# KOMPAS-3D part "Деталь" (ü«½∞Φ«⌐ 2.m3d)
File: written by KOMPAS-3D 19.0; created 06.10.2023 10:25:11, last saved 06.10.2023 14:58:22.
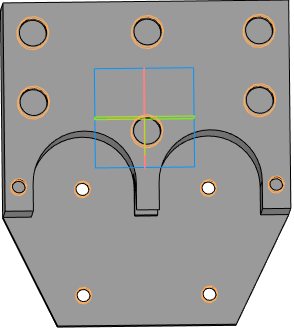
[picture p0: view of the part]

Document properties: Автор: admin; Организация: Hewlett-Packard Company; Полное имя файла: C:\Users\Petrenko-VE\Documents\Большой_2.m3d

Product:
- Part/product: Деталь
    Масса: 13.4529

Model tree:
1. Эскиз:1
2. Элемент выдавливания:1
     Расстояние 1 = 25
3. Эскиз:2  (with: Элемент выдавливания:1)
4. Элемент выдавливания:2
     Расстояние 1 = 100
5. Эскиз:3  (with: Элемент выдавливания:1, Элемент выдавливания:2)
6. Элемент выдавливания:3
     Расстояние 2 = 40
7. Эскиз:4  (with: Элемент выдавливания:3)
8. Элемент выдавливания:4
     Расстояние 1 = 5
9. Эскиз:5  (with: Элемент выдавливания:3)
10. Элемент выдавливания:5
     Расстояние 1 = 5
11. Эскиз:6  (with: Элемент выдавливания:1)
12. Элемент выдавливания:6
     Расстояние 1 = 10
13. Эскиз:7  (with: Элемент выдавливания:5)
14. Элемент выдавливания:7
     Расстояние 2 = 20
15. Эскиз:8  (with: Элемент выдавливания:4)
16. Элемент выдавливания:8
     Расстояние 2 = 20
17. Эскиз:9  (with: Элемент выдавливания:1, Элемент выдавливания:2, Элемент выдавливания:6)
18. Элемент выдавливания:9
     Расстояние 2 = 5
19. Фаска:1  (with: Элемент выдавливания:8, Элемент выдавливания:7)
     Угол = 45; Длина 1 = 1; Длина 2 = 1
20. Эскиз:10  (with: Элемент выдавливания:5, Фаска:1)
21. Элемент выдавливания:10
     Расстояние 2 = 145
22. Эскиз:11  (with: Элемент выдавливания:4, Фаска:1)
23. Элемент выдавливания:11
     Расстояние 2 = 145
24. Эскиз:12  (with: Элемент выдавливания:9, Элемент выдавливания:10, Элемент выдавливания:11)
25. Элемент выдавливания:12
     Расстояние 1 = 105
26. Эскиз:13  (with: Элемент выдавливания:12, Элемент выдавливания:2)
27. Элемент выдавливания:13
     Расстояние 1 = 30
28. Эскиз:14  (with: Элемент выдавливания:9, Элемент выдавливания:12)
29. Элемент выдавливания:14
     Расстояние 1 = 105
30. Эскиз:15  (with: Элемент выдавливания:1, Элемент выдавливания:6)
31. Элемент выдавливания:15
     Расстояние 1 = 12
32. Эскиз:16  (with: Элемент выдавливания:15)
33. Элемент выдавливания:16
     Расстояние 2 = 40.25
34. Эскиз:17  (with: Элемент выдавливания:9, Элемент выдавливания:12)
35. Элемент выдавливания:17
     Расстояние 1 = 105
36. Эскиз:18  (with: Элемент выдавливания:1, Элемент выдавливания:6)
37. Элемент выдавливания:18
     Расстояние 1 = 12
38. Эскиз:19  (with: Элемент выдавливания:18)
39. Элемент выдавливания:19
     Расстояние 2 = 40.25
40. Эскиз:20  (with: Элемент выдавливания:1, Элемент выдавливания:15, Элемент выдавливания:18)
41. Элемент выдавливания:20
     Расстояние 1 = 60
42. Эскиз:21  (with: Элемент выдавливания:15, Элемент выдавливания:20)
43. Элемент выдавливания:21
     Расстояние 2 = 144
44. Элемент выдавливания:22  (with: Элемент выдавливания:6)
     Расстояние 1 = 55
45. Эскиз:22  (with: Элемент выдавливания:9, Элемент выдавливания:11)
46. Элемент выдавливания:23
     Расстояние 2 = 40
47. Условное изображение резьбы:1  (with: Элемент выдавливания:23)  (labels: M8; cil0_24705-2004 coarse)
     Длина резьбы = 20; Шаг резьбы = 1.25; Номинальный диаметр резьбы = 8
48. Подгонка:1  (with: Элемент выдавливания:23)
49. Условное изображение резьбы:2  (with: Элемент выдавливания:23)  (labels: M8; cil0_24705-2004 coarse)
     Длина резьбы = 20; Шаг резьбы = 1.25; Номинальный диаметр резьбы = 8
50. Подгонка:2  (with: Элемент выдавливания:23)
51. Элемент выдавливания:27  (with: Элемент выдавливания:2)
     Расстояние 1 = 10
52. Эскиз:25  (with: Элемент выдавливания:12, Элемент выдавливания:22)
53. Элемент выдавливания:28
54. Эскиз:26  (with: Элемент выдавливания:9, Элемент выдавливания:22, Элемент выдавливания:16, Элемент выдавливания:19)
55. Элемент выдавливания:29
     Расстояние 2 = 40
56. Эскиз:30  (with: Элемент выдавливания:15, Элемент выдавливания:27, Элемент выдавливания:29)
57. Элемент выдавливания:33
     Расстояние 2 = 40.25
58. Эскиз:31  (with: Элемент выдавливания:9, Элемент выдавливания:12, Элемент выдавливания:28, Элемент выдавливания:33)
59. Элемент выдавливания:34
     Расстояние 1 = 115
60. Эскиз:32  (with: Элемент выдавливания:18, Элемент выдавливания:27, Элемент выдавливания:29)
61. Элемент выдавливания:35
     Расстояние 2 = 40.25
62. Эскиз:33  (with: Элемент выдавливания:9, Элемент выдавливания:12, Элемент выдавливания:28, Элемент выдавливания:35)
63. Элемент выдавливания:36
     Расстояние 1 = 115
64. Элемент выдавливания:37  (with: Элемент выдавливания:13)
     Расстояние 1 = 95
65. Эскиз:34  (with: Элемент выдавливания:28)
66. Элемент выдавливания:38
     Расстояние 2 = 20
67. Эскиз:35  (with: Элемент выдавливания:12, Элемент выдавливания:37)
68. Элемент выдавливания:39
     Расстояние 1 = 30
69. Эскиз:36  (with: Элемент выдавливания:9, Элемент выдавливания:12)
70. Элемент выдавливания:40
     Расстояние 2 = 40
71. Эскиз:37  (with: Элемент выдавливания:21)
72. Элемент выдавливания:41
     Расстояние 2 = 160
73. Условное изображение резьбы:3  (with: Элемент выдавливания:40, Элемент выдавливания:41)  (labels: M8; cil0_24705-2004 coarse)
     Длина резьбы = 20; Шаг резьбы = 1.25; Номинальный диаметр резьбы = 8
74. Подгонка:3  (with: Элемент выдавливания:40)
75. Условное изображение резьбы:4  (with: Элемент выдавливания:40, Элемент выдавливания:41)  (labels: M8; cil0_24705-2004 coarse)
     Длина резьбы = 20; Шаг резьбы = 1.25; Номинальный диаметр резьбы = 8
76. Подгонка:4  (with: Элемент выдавливания:40)
77. Эскиз:38  (with: Элемент выдавливания:27, Элемент выдавливания:33, Элемент выдавливания:35)
78. Элемент выдавливания:42
     Расстояние 2 = 30
79. Условное изображение резьбы:5  (with: Элемент выдавливания:42)  (labels: M16; cil0_24705-2004 coarse)
     Длина резьбы = 30; Шаг резьбы = 2; Номинальный диаметр резьбы = 16
80. Подгонка:5  (with: Элемент выдавливания:42)
81. Условное изображение резьбы:6  (with: Элемент выдавливания:42)  (labels: M16; cil0_24705-2004 coarse)
     Длина резьбы = 30; Шаг резьбы = 2; Номинальный диаметр резьбы = 16
82. Подгонка:6  (with: Элемент выдавливания:42)
83. Условное изображение резьбы:7  (with: Элемент выдавливания:42)  (labels: M16; cil0_24705-2004 coarse)
     Длина резьбы = 30; Шаг резьбы = 2; Номинальный диаметр резьбы = 16
84. Подгонка:7  (with: Элемент выдавливания:42)
85. Условное изображение резьбы:8  (with: Элемент выдавливания:42)  (labels: M16; cil0_24705-2004 coarse)
     Длина резьбы = 30; Шаг резьбы = 2; Номинальный диаметр резьбы = 16
86. Подгонка:8  (with: Элемент выдавливания:42)
87. Условное изображение резьбы:9  (with: Элемент выдавливания:42)  (labels: M16; cil0_24705-2004 coarse)
     Длина резьбы = 30; Шаг резьбы = 2; Номинальный диаметр резьбы = 16
88. Подгонка:9  (with: Элемент выдавливания:42)
89. Условное изображение резьбы:10  (with: Элемент выдавливания:42)  (labels: M16; cil0_24705-2004 coarse)
     Длина резьбы = 30; Шаг резьбы = 2; Номинальный диаметр резьбы = 16
90. Подгонка:10  (with: Элемент выдавливания:42)
91. Условное изображение резьбы:11  (with: Элемент выдавливания:42)  (labels: M8; cil0_24705-2004 coarse)
     Длина резьбы = 30; Шаг резьбы = 1.25; Номинальный диаметр резьбы = 8
92. Подгонка:11  (with: Элемент выдавливания:42)
93. Условное изображение резьбы:12  (with: Элемент выдавливания:42)  (labels: M8; cil0_24705-2004 coarse)
     Длина резьбы = 30; Шаг резьбы = 1.25; Номинальный диаметр резьбы = 8
94. Подгонка:12  (with: Элемент выдавливания:42)
95. Эскиз:39  (with: Элемент выдавливания:27)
